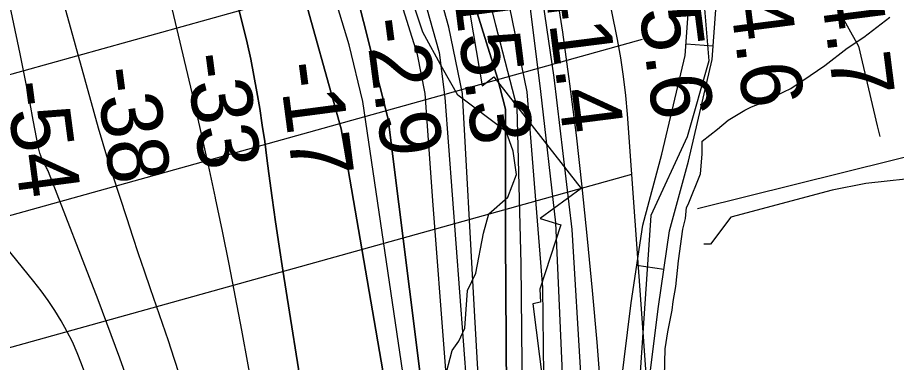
# Model space of a CAD drawing. Extents: x 3250478 to 3288318, y 788638 to 816472.
# Drawn here: x 3276625 to 3277589, y 803749 to 804127 of the extents above; entities that cross this region are included whole.
import ezdxf

# ---------------------------------------------------------------- set-up
doc = ezdxf.new("R2010")
doc.units = 0
for name, color, linetype in [('V-RIVR-EDGE', 7, 'Continuous'), ('V-RIVR-RANG', 7, 'Continuous'), ('V-ROAD-CNTR', 7, 'Continuous'), ('V-RRAP-RVMT', 7, 'Continuous'), ('V-SITE-VEGE', 7, 'Continuous'), ('V-TOPO-DPTH', 7, 'Continuous'), ('V-TOPO-MAJR', 7, 'Continuous'), ('V-TOPO-MINR', 7, 'Continuous'), ('V-TOPO-SHOR', 7, 'Continuous'), ('V-TOPO-WATR', 7, 'Continuous'), ('V-UTIL-LINE', 7, 'Continuous')]:
    doc.layers.add(name, color=color, linetype=linetype)

msp = doc.modelspace()

# ---------------------------------------------------------------- linework, layer by layer
at = {"layer": 'V-RIVR-EDGE'}
msp.add_lwpolyline([(3277093.7, 803730.28), (3277102.04, 803762.43), (3277109.45, 803772.41), (3277116.01, 803786.74), (3277118.72, 803828.02), (3277127.89, 803847.13), (3277136.26, 803891.01), (3277142.4, 803912.29), (3277163.31, 803930.5), (3277172.5, 803955.25), (3277169.08, 803980.91), (3277161.31, 804002.23), (3277108.38, 804042.35), (3277091.5, 804071.95), (3277069.86, 804111.12), (3277051.31, 804167.24)], dxfattribs=at)
at = {"layer": 'V-ROAD-CNTR'}
for p, q in [((3277358.63, 804098.49), (3277388.55, 804096.26)), ((3277304.62, 803855.86), (3277334.3, 803851.49))]:
    msp.add_line(p, q, dxfattribs=at)
for points in [[(3277392.91, 801999.9), (3277380.13, 802299.72), (3277372.29, 802418.39), (3277370.47, 802489.59), (3277368.16, 802710.81), (3277357.29, 802858.42), (3277325.06, 803070.98), (3277305.47, 803189.65), (3277287.6, 803279.28), (3277276.49, 803353.07), (3277271.84, 803390.05), (3277271.11, 803434.65), (3277277.15, 803549.38), (3277286.86, 803719.88), (3277298.52, 803814.5), (3277311.07, 803899.69), (3277332.27, 803977.36), (3277357.69, 804085.87), (3277361.85, 804141.68)], [(3277378.48, 804141.38), (3277383.64, 804080.01), (3277359.82, 803996.62), (3277319.97, 803910.43), (3277296.27, 803561.33), (3277300.08, 803372.73), (3277314.93, 803252.32), (3277371.49, 802882.9), (3277384.78, 802697.25), (3277393.32, 802489.28), (3277402.58, 802336.83), (3277404.92, 802178.43), (3277406.66, 802052.14), (3277409.51, 801949.16), (3277423.12, 801871.68), (3277443.93, 801755.39), (3277461.26, 801657.56)], [(3277422.83, 802002.29), (3277410.09, 802301.35), (3277402.26, 802419.77), (3277400.46, 802490.13), (3277398.15, 802712.07), (3277387.13, 802861.78), (3277354.69, 803075.67), (3277334.99, 803195.02), (3277317.16, 803284.45), (3277306.21, 803357.18), (3277301.81, 803392.17), (3277301.13, 803434.1), (3277307.1, 803547.74), (3277316.75, 803717.19), (3277328.25, 803810.47), (3277340.49, 803893.53), (3277361.36, 803969.99), (3277387.43, 804081.31), (3277391.88, 804141.03)]]:
    msp.add_lwpolyline(points, dxfattribs=at)
at = {"layer": 'V-RRAP-RVMT'}
for p, q in [((3277098.27, 804267.83), (3277135.14, 804052.52)), ((3277135.14, 804052.52), (3277147.71, 804062.29)), ((3277147.71, 804062.29), (3277243.59, 803939.89)), ((3277243.59, 803939.89), (3277198.51, 803907.03)), ((3277221.38, 803900), (3277198.07, 803829.44)), ((3277198.51, 803907.03), (3277221.38, 803900)), ((3277198.07, 803829.44), (3277198.86, 803815.18)), ((3277198.86, 803815.18), (3277190.56, 803813.56)), ((3277190.56, 803813.56), (3277209.43, 803666.88))]:
    msp.add_line(p, q, dxfattribs=at)
at = {"layer": 'V-SITE-VEGE'}
for p, q in [((3277553.6, 804105.8), (3277582.41, 804127.87)), ((3277535.44, 804093.62), (3277553.6, 804105.8)), ((3277510.9, 804074.86), (3277535.44, 804093.62)), ((3277494.88, 804063.8), (3277510.9, 804074.86)), ((3277473.51, 804049.41), (3277494.88, 804063.8)), ((3277444.58, 804034.9), (3277466, 804046.05)), ((3277466, 804046.05), (3277473.51, 804049.41)), ((3277430.63, 804029.27), (3277444.58, 804034.9)), ((3277404.95, 804014.81), (3277423.13, 804025.91)), ((3277423.13, 804025.91), (3277430.63, 804029.27)), ((3277393.23, 804004.9), (3277404.95, 804014.81)), ((3277376.16, 803991.66), (3277393.23, 804004.9)), ((3277376.38, 803977.62), (3277376.16, 803991.66)), ((3277374.58, 803955.99), (3277376.38, 803977.62)), ((3277361.08, 803922.29), (3277374.58, 803955.99)), ((3277358.09, 803907.12), (3277358.98, 803919.01)), ((3277358.98, 803919.01), (3277361.08, 803922.29)), ((3277355.05, 803895.19), (3277358.09, 803907.12)), ((3277350.21, 803860.55), (3277355.05, 803895.19)), ((3277347.43, 803832.42), (3277350.21, 803860.55)), ((3277344.45, 803816.17), (3277347.43, 803832.42)), ((3277343.53, 803806.43), (3277344.45, 803816.17)), ((3277338.51, 803782.59), (3277343.53, 803806.43)), ((3277335.57, 803764.18), (3277338.51, 803782.59)), ((3277334.99, 803733.93), (3277335.57, 803764.18))]:
    msp.add_line(p, q, dxfattribs=at)
at = {"layer": 'V-TOPO-DPTH'}
for points in [[(3276892.9, 804781.29), (3277087.64, 804088.93), (3277094.06, 804039.6), (3277126.11, 803612.77), (3277153.89, 803239.56), (3277164.59, 803151.62), (3277233.04, 802546.76), (3277273.64, 802019.12), (3277277.9, 801899.01), (3277327.13, 801555.82), (3277348.53, 801405.68), (3277380.66, 801251.24), (3277384.94, 801221.21), (3277410.5, 800597.06)], [(3276892.9, 804781.29), (3277087.64, 804088.93), (3277094.06, 804039.6), (3277126.11, 803612.77), (3277153.89, 803239.56), (3277164.59, 803151.62), (3277233.04, 802546.76), (3277273.64, 802019.12), (3277277.9, 801899.01), (3277327.13, 801555.82), (3277348.53, 801405.68), (3277380.66, 801251.24), (3277384.94, 801221.21), (3277410.5, 800597.06)], [(3278043.49, 798542.65), (3277830.49, 799256.42), (3277566.87, 799908.53), (3277517.59, 800082.27), (3277468.3, 800241), (3277429.79, 800571.32), (3277421.23, 800642.1), (3277410.61, 800987.42), (3277399.95, 801210.49), (3277393.53, 801266.25), (3277350.72, 801538.66), (3277329.31, 801695.24), (3277325.06, 801815.35), (3277325.09, 801924.73), (3277278.09, 802561.76), (3277267.39, 802638.98), (3277188.19, 803185.93), (3277171.09, 803391.84), (3277162.57, 803604.18), (3277160.51, 803885.15), (3277160.55, 804026.71), (3277151.98, 804061.03), (3277098.41, 804232.63), (3276937.71, 804777.47)], [(3277041.82, 802822.9), (3276997.74, 803084.88), (3276988.97, 803136.32), (3276980.05, 803187.74), (3276970.91, 803239.12), (3276961.63, 803290.47), (3276871.21, 803784.49), (3276864.41, 803820.75), (3276857.4, 803856.97), (3276850.08, 803893.13), (3276842.56, 803929.25), (3276842.43, 803929.84), (3276834.68, 803965.6), (3276826.77, 804001.32), (3276818.61, 804036.99), (3276810.29, 804072.63), (3276651.58, 804741.55)], [(3277041.82, 802822.9), (3276997.74, 803084.88), (3276988.97, 803136.32), (3276980.05, 803187.74), (3276970.91, 803239.12), (3276961.63, 803290.47), (3276871.21, 803784.49), (3276864.41, 803820.75), (3276857.4, 803856.97), (3276850.08, 803893.13), (3276842.56, 803929.25), (3276842.43, 803929.84), (3276834.68, 803965.6), (3276826.77, 804001.32), (3276818.61, 804036.99), (3276810.29, 804072.63), (3276651.58, 804741.55)], [(3276847.78, 804709.98), (3276986.87, 804194.06), (3277031.86, 804016.03), (3277102.47, 803454.06), (3277138.86, 803192.38), (3277158.11, 803005.78), (3277207.29, 802486.71), (3277260.73, 801884), (3277305.66, 801504.35), (3277359.2, 801223.37), (3277382.64, 800685.01), (3277391.17, 800526.29), (3277412.53, 800204.56), (3277453.21, 799970.76), (3277491.77, 799816.32), (3277536.77, 799668.32), (3277575.35, 799580.37), (3277620.37, 799498.85), (3277676.11, 799421.62), (3277755.44, 799312.21), (3277770.45, 799280.03), (3277813.29, 799119.16), (3277973.95, 798523.47)], [(3277973.95, 798523.47), (3277813.29, 799119.16), (3277770.45, 799280.03), (3277755.44, 799312.21), (3277676.11, 799421.62), (3277620.37, 799498.85), (3277575.35, 799580.37), (3277536.77, 799668.32), (3277491.77, 799816.32), (3277453.21, 799970.76), (3277412.53, 800204.56), (3277391.17, 800526.29), (3277382.64, 800685.01), (3277359.2, 801223.37), (3277305.66, 801504.35), (3277260.73, 801884), (3277207.29, 802486.71), (3277158.11, 803005.78), (3277138.86, 803192.38), (3277102.47, 803454.06), (3277031.86, 804016.03), (3276986.87, 804194.06), (3276847.78, 804709.98)], [(3277053.28, 802996.4), (3277037.14, 803094.17), (3277021.14, 803191.96), (3277005.36, 803289.79), (3276989.72, 803387.64), (3276916.3, 803850.23), (3276912.21, 803876.73), (3276908.27, 803903.25), (3276904.57, 803929.8), (3276901.01, 803956.38), (3276898.84, 803973.18), (3276896.37, 803991.35), (3276893.76, 804009.5), (3276890.92, 804027.62), (3276887.94, 804045.72), (3276884.63, 804063.75), (3276881.03, 804081.73), (3276877.02, 804099.61), (3276872.72, 804117.43), (3276725.68, 804696.95)], [(3276725.68, 804696.95), (3276872.72, 804117.43), (3276877.02, 804099.61), (3276881.03, 804081.73), (3276884.63, 804063.75), (3276887.94, 804045.72), (3276890.92, 804027.62), (3276893.76, 804009.5), (3276896.37, 803991.35), (3276898.84, 803973.18), (3276901.01, 803956.38), (3276904.57, 803929.8), (3276908.27, 803903.25), (3276912.21, 803876.73), (3276916.3, 803850.23), (3276989.72, 803387.64), (3277005.36, 803289.79), (3277021.14, 803191.96), (3277037.14, 803094.17), (3277053.28, 802996.4)], [(3277354.75, 800674.29), (3277341.97, 800959.56), (3277324.89, 801246.97), (3277301.33, 801364.94), (3277271.37, 801568.71), (3277239.28, 801871.14), (3277177.28, 802553.21), (3277170.88, 802654.02), (3277136.67, 803027.23), (3277119.56, 803196.68), (3276980.38, 804005.32), (3276797.47, 804660.41)], [(3276797.47, 804660.41), (3276980.38, 804005.32), (3277119.56, 803196.68), (3277136.67, 803027.23), (3277170.88, 802654.02), (3277177.28, 802553.21), (3277239.28, 801871.14), (3277271.37, 801568.71), (3277301.33, 801364.94), (3277324.89, 801246.97), (3277341.97, 800959.56), (3277354.75, 800674.29)]]:
    msp.add_lwpolyline(points, dxfattribs=at)
at = {"layer": 'V-TOPO-MAJR'}
for points in [[(3276825.61, 803666.12), (3276797.11, 803753.57), (3276790.79, 803772.74), (3276784.39, 803791.89), (3276777.86, 803810.99), (3276771.24, 803830.06), (3276764.62, 803849.13), (3276758.1, 803868.24), (3276751.71, 803887.38), (3276745.4, 803906.56), (3276729.87, 803954.39), (3276724.43, 803971.56), (3276719.13, 803988.77), (3276714.06, 804006.04), (3276709.14, 804023.37), (3276627.34, 804318.96)], [(3277290.27, 802862.08), (3277253.53, 803138.54), (3277251.81, 803151.21), (3277250.02, 803163.87), (3277248.16, 803176.51), (3277246.24, 803189.15), (3277244.34, 803201.79), (3277242.52, 803214.45), (3277240.84, 803227.12), (3277239.24, 803239.8), (3277237.35, 803255.44), (3277234.99, 803275.97), (3277232.79, 803296.51), (3277230.82, 803317.07), (3277229.01, 803337.65), (3277222.87, 803745.58), (3277215.72, 803902.2), (3277199.4, 804046.25), (3277180.85, 804196.04)]]:
    msp.add_lwpolyline(points, dxfattribs=at)
at = {"layer": 'V-TOPO-MINR'}
for points in [[(3277012.07, 804812.64), (3277098.48, 804462.13), (3277184.15, 804046.01), (3277201.25, 803831.52), (3277207.52, 803284.59), (3277220.36, 803181.63), (3277250.34, 803016.47), (3277308.13, 802593.92), (3277380.82, 801791.74), (3277395.74, 801493.6), (3277434.27, 801227.63), (3277440.64, 800976.69), (3277457.7, 800663.54), (3277476.95, 800455.48), (3277521.93, 800249.57), (3277620.5, 799940.68), (3277903.42, 799275.71), (3277929.13, 799177.04), (3277978.39, 798930.37), (3278074.36, 798551.17)], [(3278059.89, 798547.18), (3277851.95, 799275.72), (3277581.89, 799929.97), (3277496.19, 800262.44), (3277461.93, 800457.63), (3277447.45, 800598.15), (3277408.54, 801244.8), (3277389.28, 801375.64), (3277350.76, 801675.93), (3277342.23, 801868.96), (3277290.96, 802566.05), (3277250.3, 802883.49), (3277196.78, 803218.1), (3277181.83, 803456.18), (3277177.66, 803857.27), (3277173.42, 804028.85), (3277149.85, 804118.94), (3276984.34, 804796.07)], [(3276937.71, 804777.47), (3277098.41, 804232.63), (3277151.98, 804061.03), (3277160.55, 804026.71), (3277160.51, 803885.15), (3277162.57, 803604.18), (3277171.09, 803391.84), (3277188.19, 803185.93), (3277267.39, 802638.98), (3277278.09, 802561.76), (3277325.09, 801924.73), (3277325.06, 801815.35), (3277329.31, 801695.24), (3277350.72, 801538.66), (3277393.53, 801266.25), (3277399.95, 801210.49), (3277410.61, 800987.42), (3277421.23, 800642.1), (3277429.79, 800571.32), (3277468.3, 800241), (3277517.59, 800082.27), (3277566.87, 799908.53), (3277830.49, 799256.42), (3278043.49, 798542.65)], [(3278027.25, 798538.17), (3277935.46, 798805.98), (3277806.9, 799254.29), (3277796.19, 799290.75), (3277609.72, 799736.93), (3277513.28, 800009.35), (3277446.85, 800219.56), (3277436.18, 800393.3), (3277416.94, 800624.94), (3277391.38, 801225.5), (3277350.69, 801463.59), (3277288.62, 801905.44), (3277256.59, 802379.46), (3277241.64, 802615.39), (3277166.75, 803211.68), (3277145.38, 803477.64), (3277126.17, 803812.24), (3277113.37, 804043.88), (3277098.38, 804116.81), (3277001.96, 804462.16), (3276914.11, 804773.18)], [(3277041.82, 802822.9), (3276997.74, 803084.88), (3276988.97, 803136.32), (3276980.05, 803187.74), (3276970.91, 803239.12), (3276961.63, 803290.47), (3276871.21, 803784.49), (3276864.41, 803820.75), (3276857.4, 803856.97), (3276850.08, 803893.13), (3276842.56, 803929.25), (3276842.43, 803929.84), (3276834.68, 803965.6), (3276826.77, 804001.32), (3276818.61, 804036.99), (3276810.29, 804072.63), (3276651.58, 804741.55)], [(3276847.78, 804709.98), (3276986.87, 804194.06), (3277031.86, 804016.03), (3277102.47, 803454.06), (3277138.86, 803192.38), (3277158.11, 803005.78), (3277207.29, 802486.71), (3277260.73, 801884), (3277305.66, 801504.35), (3277359.2, 801223.37), (3277382.64, 800685.01), (3277391.17, 800526.29), (3277412.53, 800204.56), (3277453.21, 799970.76), (3277491.77, 799816.32), (3277536.77, 799668.32), (3277575.35, 799580.37), (3277620.37, 799498.85), (3277676.11, 799421.62), (3277755.44, 799312.21), (3277770.45, 799280.03), (3277813.29, 799119.16), (3277973.95, 798523.47)], [(3277053.28, 802996.4), (3277037.14, 803094.17), (3277021.14, 803191.96), (3277005.36, 803289.79), (3276989.72, 803387.64), (3276916.3, 803850.23), (3276912.21, 803876.73), (3276908.27, 803903.25), (3276904.57, 803929.8), (3276901.01, 803956.38), (3276898.84, 803973.18), (3276896.37, 803991.35), (3276893.76, 804009.5), (3276890.92, 804027.62), (3276887.94, 804045.72), (3276884.63, 804063.75), (3276881.03, 804081.73), (3276877.02, 804099.61), (3276872.72, 804117.43), (3276725.68, 804696.95)], [(3276760, 803689.9), (3276737.37, 803754), (3276713.61, 803817.71), (3276659.11, 803958.29), (3276658.66, 803959.38), (3276658.17, 803960.45), (3276657.63, 803961.5), (3276657.05, 803962.52), (3276656.47, 803963.55), (3276655.9, 803964.58), (3276655.36, 803965.63), (3276654.85, 803966.69), (3276651.97, 803972.8), (3276650.77, 803975.63), (3276649.71, 803978.51), (3276648.88, 803981.45), (3276648.2, 803984.45), (3276642.48, 804014.76), (3276638.99, 804032.93), (3276635.43, 804051.09), (3276631.74, 804069.23), (3276627.98, 804087.35), (3276503.94, 804675.04)], [(3277370.7, 803026.54), (3277365.19, 803076.2), (3277359.63, 803125.85), (3277351.3, 803199.58), (3277349.96, 803212.37), (3277348.74, 803225.18), (3277347.73, 803238.01), (3277346.86, 803250.84), (3277339.51, 803372.01), (3277334.94, 803445.44), (3277330.2, 803518.85), (3277325.22, 803592.24), (3277320.07, 803665.63), (3277294.49, 804021.28), (3277292.61, 804041.93), (3277290.21, 804062.52), (3277287.02, 804082.99), (3277283.3, 804103.4), (3277169.16, 804668.97)], [(3276797.47, 804660.41), (3276980.38, 804005.32), (3277119.56, 803196.68), (3277136.67, 803027.23), (3277170.88, 802654.02), (3277177.28, 802553.21), (3277239.28, 801871.14), (3277271.37, 801568.71), (3277301.33, 801364.94), (3277324.89, 801246.97), (3277341.97, 800959.56), (3277354.75, 800674.29)], [(3277359.09, 800848.02), (3277339.91, 801246.96), (3277322.77, 801330.62), (3277294.95, 801519.37), (3277264.99, 801766.03), (3277245.74, 801948.35), (3277192.29, 802555.35), (3277155.95, 802943.58), (3277123.86, 803237.43), (3277051.07, 803715.74), (3277003.98, 804035.34), (3276988.98, 804097.54), (3276928.99, 804294.88)], [(3277307.34, 802879.46), (3277266.64, 803187.97), (3277265.99, 803192.72), (3277265.33, 803197.48), (3277264.63, 803202.23), (3277263.91, 803206.97), (3277263.21, 803211.72), (3277262.53, 803216.47), (3277261.91, 803221.23), (3277261.32, 803226), (3277260.65, 803231.73), (3277259.79, 803239.37), (3277259, 803247.02), (3277258.29, 803254.68), (3277257.65, 803262.34), (3277243.57, 803731.17), (3277233.72, 803895), (3277213.97, 804061.52), (3277189.71, 804226.25)], [(3277480.73, 804216.98), (3277547.86, 804095.9), (3277568.42, 804008.67), (3277571.09, 803996.76)], [(3277359.26, 802733.23), (3277311.48, 803150.09), (3277307.64, 803185.37), (3277304.07, 803220.67), (3277300.9, 803256.01), (3277297.99, 803291.38), (3277265.64, 803714.48), (3277261.03, 803771.31), (3277256.08, 803828.11), (3277250.62, 803884.87), (3277244.81, 803941.59), (3277238.32, 803998.23), (3277231.25, 804054.8), (3277223.32, 804111.25), (3277214.82, 804167.63)], [(3277397.64, 800650.69), (3277376.36, 801219.07), (3277369.94, 801253.39), (3277331.39, 801446.44), (3277269.32, 801899.01), (3277226.56, 802377.32), (3277198.77, 802703.34), (3277156, 803136.61), (3277145.3, 803205.25), (3277119.62, 803421.88), (3277081.16, 803921.64), (3277072.62, 804043.9), (3277064.05, 804086.79), (3277044.77, 804149)], [(3276855.07, 803174.2), (3276846.7, 803213.01), (3276837.92, 803251.73), (3276793.13, 803441.94), (3276778.84, 803498.04), (3276763.19, 803553.73), (3276745.52, 803608.82), (3276726.49, 803663.49), (3276695.52, 803747.52), (3276690.65, 803759.73), (3276685.37, 803771.74), (3276679.46, 803783.46), (3276673.13, 803794.98), (3276666.23, 803806.18), (3276659, 803817.14), (3276651.25, 803827.75), (3276643.17, 803838.12), (3276561.74, 803937.59)]]:
    msp.add_lwpolyline(points, dxfattribs=at)
at = {"layer": 'V-TOPO-SHOR'}
msp.add_lwpolyline([(3278141.34, 804049.14), (3278156.16, 803975.05), (3278170.98, 803908.36), (3278148.75, 803900.95), (3278111.7, 803915.77), (3278059.84, 803908.36), (3278030.2, 803908.36), (3278000.56, 803945.41), (3277978.34, 803982.46), (3277926.47, 804012.09), (3277837.56, 803967.64), (3277770.87, 803975.05), (3277681.96, 803975.05), (3277622.69, 803952.82), (3277556, 803945.41), (3277518.95, 803938), (3277407.81, 803908.36), (3277385.59, 803878.73), (3277378.18, 803878.73)], dxfattribs=at)
at = {"layer": 'V-TOPO-WATR'}
msp.add_lwpolyline([(3276892.9, 804781.29), (3277087.64, 804088.93), (3277094.06, 804039.6), (3277126.11, 803612.77), (3277153.89, 803239.56), (3277164.59, 803151.62), (3277233.04, 802546.76), (3277273.64, 802019.12), (3277277.9, 801899.01), (3277327.13, 801555.82), (3277348.53, 801405.68), (3277380.66, 801251.24), (3277384.94, 801221.21), (3277410.5, 800597.06)], dxfattribs=at)
at = {"layer": 'V-UTIL-LINE'}
for p, q in [((3277287.57, 804251.48), (3274176.39, 803385.36)), ((3277310.37, 804103.33), (3274199.18, 803237.21)), ((3277298.97, 803955.18), (3274187.79, 803089.06))]:
    msp.add_line(p, q, dxfattribs=at)
msp.add_lwpolyline([(3277371.35, 803918.15), (3278227.12, 804130.28), (3278966.05, 804313.1), (3279791.62, 804514.54), (3280404.5, 804671.43), (3280632.47, 804743.81), (3281799.44, 805040.2)], dxfattribs=at)

# ---------------------------------------------------------------- texts
at = {"layer": 'V-RIVR-RANG'}
for s, rotation, p in [('44.7', 277.23833, (3277499.67, 804209.43)), ('44.6', 277.23833, (3277400.27, 804198.42)), ('45.6', 277.23833, (3277301.09, 804185.57)), ('41.4', 277.23833, (3277202.15, 804170.9)), ('15.3', 277.23833, (3277102.98, 804158.05)), ('-2.9', 277.49331, (3277005.99, 804124.6)), ('-33', 277.49331, (3276809.33, 804086.09)), ('-17', 277.49331, (3276911.49, 804076.2)), ('-38', 277.49331, (3276710.5, 804070.63)), ('-54', 277.49331, (3276611.64, 804055.44))]:
    msp.add_text(s, height=67, rotation=rotation, dxfattribs=at).set_placement(p)

doc.saveas('drawing.dxf')
